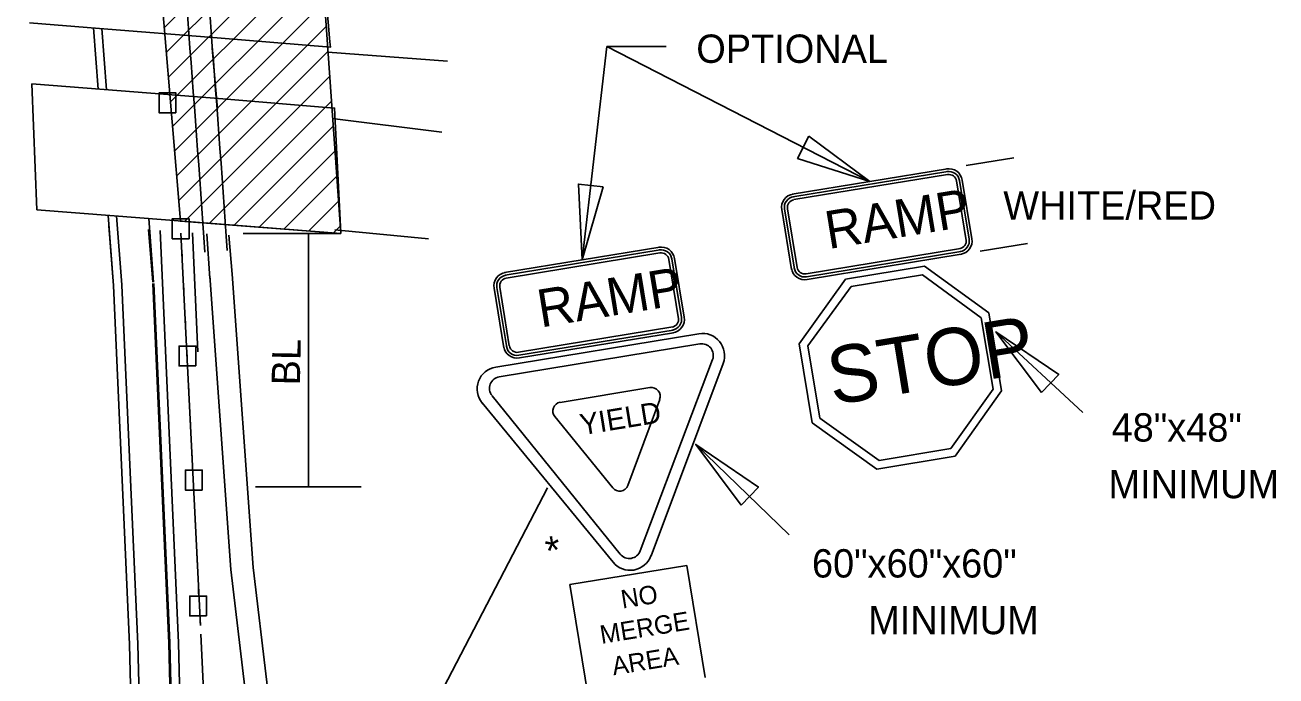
# Model space of a CAD drawing. Extents: x 612.5 to 619.9, y 600.8 to 610.9.
# Drawn here: x 615.494 to 618.141, y 606.093 to 607.471 of the extents above; entities that cross this region are included whole.
import ezdxf

# ---------------------------------------------------------------- set-up
doc = ezdxf.new("R2010")
doc.units = 0
for name, color, linetype in [('DETL-DIMS', 7, 'Continuous'), ('DETL-LINE', 7, 'Continuous'), ('DETL-NOTE', 7, 'Continuous')]:
    doc.layers.add(name, color=color, linetype=linetype)

msp = doc.modelspace()

# ---------------------------------------------------------------- linework, layer by layer
at = {"layer": 'DETL-DIMS'}
for p, q in [((616.6728, 606.9737), (616.7251, 607.4256)), ((616.7251, 607.4256), (617.2816, 607.1398)), ((616.8503, 607.4256), (616.7251, 607.4256)), ((617.4856, 607.1732), (617.5862, 607.1897)), ((616.162, 607.0297), (615.9552, 607.0297)), ((616.0936, 606.4929), (616.0936, 607.0279)), ((617.5152, 606.9922), (617.6154, 607.0086)), ((617.5486, 606.8214), (617.7323, 606.6507)), ((616.9133, 606.5829), (617.1111, 606.3914)), ((615.9818, 606.4929), (616.2054, 606.4929)), ((616.1815, 605.6878), (616.5998, 606.491))]:
    msp.add_line(p, q, dxfattribs=at)
for points in [[(617.1528, 607.2356), (617.1286, 607.1886), (617.2816, 607.1398)], [(616.7172, 607.128), (616.6648, 607.134), (616.6728, 606.9737)], [(617.6449, 606.693), (617.6813, 606.7311), (617.5486, 606.8214)], [(617.0096, 606.4546), (617.046, 606.4927), (616.9133, 606.5829)]]:
    msp.add_lwpolyline(points, close=True, dxfattribs=at)
at = {"layer": 'DETL-LINE'}
for p, q in [((615.7884, 607.4647), (616.1088, 607.7851)), ((615.7928, 607.4125), (616.1125, 607.7322)), ((615.7972, 607.3603), (616.1162, 607.6794)), ((615.8015, 607.3081), (616.12, 607.6265)), ((615.8059, 607.2559), (616.1237, 607.5737)), ((615.8103, 607.2037), (616.1274, 607.5208)), ((615.6384, 607.4649), (615.6486, 607.3353)), ((615.6563, 607.4634), (615.6665, 607.3339)), ((615.8147, 607.1515), (616.1311, 607.468)), ((615.819, 607.0993), (616.1348, 607.4151)), ((615.8896, 607.4221), (615.9011, 607.2929)), ((615.8896, 607.4221), (615.9011, 607.2929)), ((615.8896, 607.4221), (615.9011, 607.2929)), ((615.8317, 607.0554), (616.1386, 607.3623)), ((615.8841, 607.0513), (616.1423, 607.3094)), ((615.9366, 607.0472), (616.146, 607.2566)), ((615.9891, 607.0431), (616.1497, 607.2037)), ((617.4458, 607.1667), (617.1173, 607.1128)), ((616.0416, 607.039), (616.1534, 607.1509)), ((617.1185, 607.1071), (617.4467, 607.161)), ((617.1211, 607.1012), (617.446, 607.1546)), ((617.465, 607.1408), (617.4856, 607.0149)), ((617.4651, 607.1406), (617.465, 607.1408)), ((617.4716, 607.1418), (617.492, 607.0175)), ((617.4977, 607.0185), (617.4774, 607.1428)), ((616.0941, 607.035), (616.1571, 607.098)), ((615.6695, 607.068), (615.6812, 606.9196)), ((615.6875, 607.0666), (615.6988, 606.921)), ((615.7555, 607.0613), (615.766, 606.9262)), ((617.0954, 607.0801), (617.1162, 606.9533)), ((617.1219, 606.9545), (617.1012, 607.0811)), ((617.1276, 606.9578), (617.1072, 607.082)), ((615.6712, 607.0457), (615.6812, 606.9196)), ((615.6712, 607.0457), (615.6812, 606.9196)), ((615.6712, 607.0457), (615.6812, 606.9196)), ((615.7552, 607.0381), (615.764, 606.9262)), ((616.1466, 607.0309), (616.1609, 607.0452)), ((616.3477, 607.018), (616.1494, 607.0374)), ((615.8648, 606.1999), (615.8238, 607.0299)), ((615.8482, 607.0308), (615.8594, 606.779)), ((615.8851, 606.9346), (615.8786, 607.0285)), ((615.9248, 607.0259), (615.932, 606.9434)), ((615.9248, 607.0259), (615.932, 606.9434)), ((615.9248, 607.0259), (615.932, 606.9434)), ((615.9248, 607.0259), (615.932, 606.9434)), ((616.837, 607.0006), (616.5085, 606.9467)), ((616.5097, 606.941), (616.8378, 606.9948)), ((616.5123, 606.9352), (616.8372, 606.9885)), ((617.4737, 606.998), (617.1468, 606.9444)), ((617.4741, 606.9914), (617.1479, 606.9379)), ((617.1488, 606.9321), (617.4751, 606.9856)), ((616.8561, 606.9747), (616.8768, 606.8487)), ((616.8563, 606.9745), (616.8561, 606.9747)), ((616.8627, 606.9758), (616.8832, 606.8516)), ((616.889, 606.8525), (616.8686, 606.9768)), ((617.2305, 606.9332), (617.3974, 606.9606)), ((617.2305, 606.9332), (617.3974, 606.9606)), ((617.3974, 606.9606), (617.5334, 606.8615)), ((617.3974, 606.9606), (617.5334, 606.8615)), ((617.2305, 606.9332), (617.1321, 606.7962)), ((617.1321, 606.7962), (617.2305, 606.9332)), ((617.242, 606.917), (617.3928, 606.9417)), ((617.3928, 606.9417), (617.5175, 606.8512)), ((616.4866, 606.914), (616.5074, 606.7872)), ((616.5131, 606.7884), (616.4923, 606.915)), ((616.5187, 606.7918), (616.4984, 606.916)), ((617.242, 606.917), (617.1505, 606.7915)), ((617.5175, 606.8512), (617.5424, 606.6998)), ((617.5605, 606.6962), (617.5334, 606.8615)), ((617.5334, 606.8615), (617.5605, 606.6962)), ((616.8649, 606.8319), (616.538, 606.7783)), ((616.8652, 606.8252), (616.5391, 606.7718)), ((616.4898, 606.7469), (616.9196, 606.8174)), ((616.4974, 606.7262), (616.9216, 606.7958)), ((616.54, 606.766), (616.8663, 606.8195)), ((617.1596, 606.6288), (617.1321, 606.7962)), ((617.1596, 606.6288), (617.1321, 606.7962)), ((617.1505, 606.7915), (617.1756, 606.6385)), ((616.9488, 606.7626), (616.7957, 606.3574)), ((616.8186, 606.347), (616.9714, 606.7546)), ((616.8164, 606.7033), (616.6262, 606.6721)), ((616.8164, 606.7033), (616.8164, 606.7033)), ((617.5424, 606.6998), (617.4531, 606.5742)), ((617.5605, 606.6962), (617.4623, 606.5582)), ((617.5605, 606.6962), (617.4623, 606.5582)), ((616.7382, 606.3336), (616.4612, 606.6707)), ((616.7532, 606.3507), (616.4822, 606.6862)), ((616.7694, 606.4961), (616.8369, 606.6784)), ((616.6148, 606.6419), (616.7375, 606.4908)), ((617.3012, 606.5493), (617.1756, 606.6385)), ((617.2965, 606.5309), (617.1596, 606.6288)), ((617.2965, 606.5309), (617.1596, 606.6288)), ((617.4623, 606.5582), (617.2965, 606.5309)), ((617.4623, 606.5582), (617.2965, 606.5309)), ((617.3012, 606.5493), (617.4531, 606.5742)), ((616.6468, 606.2864), (616.8941, 606.327)), ((616.8941, 606.327), (616.933, 606.0896)), ((616.6468, 606.2864), (616.6857, 606.049)), ((615.8748, 605.9976), (615.8657, 606.181))]:
    msp.add_line(p, q, dxfattribs=at)
for points in [[(616.162, 607.0297), (615.8227, 607.0555), (615.664, 608.9494), (616.0287, 608.9238)], [(615.813, 607.2851), (615.7775, 607.2851), (615.7775, 607.3273), (615.813, 607.3273)], [(615.8408, 607.0184), (615.8053, 607.0184), (615.8053, 607.0606), (615.8408, 607.0606)], [(615.8554, 606.7491), (615.8199, 606.7491), (615.8199, 606.7913), (615.8554, 606.7913)], [(615.8687, 606.4864), (615.8332, 606.4864), (615.8332, 606.5286), (615.8687, 606.5286)], [(615.878, 606.2198), (615.8425, 606.2198), (615.8425, 606.262), (615.878, 606.262)]]:
    msp.add_lwpolyline(points, close=True, dxfattribs=at)
for points in [[(615.5034, 607.4759), (615.6514, 607.4639), (615.9007, 607.4435), (616.14, 607.424), (616.139, 607.4356), (616.1204, 607.6527), (616.1179, 607.6811), (615.878, 607.6997), (615.6314, 607.7187), (615.4938, 607.7293)], [(616.1346, 607.4137), (616.3877, 607.3943)], [(615.5084, 607.3467), (615.5185, 607.0799)], [(615.5185, 607.0799), (615.6825, 607.0671), (615.9359, 607.0472), (616.162, 607.0297), (616.1606, 607.0588), (616.149, 607.2952), (615.9122, 607.3143), (615.6615, 607.3343), (615.5084, 607.3467)], [(616.144, 607.2731), (616.3762, 607.2439)], [(615.743, 602.4107), (615.7794, 602.9085), (615.8185, 603.7952), (615.8337, 604.693), (615.8344, 605.528), (615.8187, 606.1632), (615.7799, 607.0362)], [(615.8261, 606.9821), (615.8257, 606.9908)], [(615.8266, 606.9731), (615.8261, 606.9821)], [(615.8847, 606.94), (615.9293, 606.3182), (615.9874, 605.8308), (616.0364, 605.4649), (616.065, 605.3359)], [(615.932, 606.9434), (615.9765, 606.3227), (616.0345, 605.8368), (616.0832, 605.4732), (616.1113, 605.3462)], [(615.932, 606.9434), (615.9765, 606.3227), (616.0345, 605.8368), (616.0832, 605.4732), (616.1113, 605.3462)], [(615.932, 606.9434), (615.9765, 606.3227), (616.0345, 605.8368), (616.0832, 605.4732), (616.1113, 605.3462)], [(615.932, 606.9434), (615.9765, 606.3227), (616.0345, 605.8368), (616.0832, 605.4732), (616.1113, 605.3462)], [(615.6811, 606.9197), (615.715, 606.1596), (615.7306, 605.5268), (615.7303, 605.1667)], [(615.6989, 606.9205), (615.7327, 606.1602), (615.7484, 605.5269), (615.7481, 605.1667)], [(615.7641, 606.9234), (615.798, 606.1625), (615.8137, 605.5277), (615.813, 604.6932), (615.7977, 603.7958), (615.7587, 602.9098), (615.7222, 602.4111)], [(615.7662, 606.9235), (615.8, 606.1626), (615.8157, 605.5277), (615.8154, 605.1666)], [(615.8296, 606.9109), (615.8293, 606.9198)], [(615.83, 606.902), (615.8296, 606.9109)], [(615.8332, 606.8398), (615.8328, 606.8488)], [(615.8336, 606.831), (615.8332, 606.8398)], [(615.8367, 606.7688), (615.8362, 606.7776)], [(615.8371, 606.7598), (615.8367, 606.7688)], [(615.8402, 606.6976), (615.8398, 606.7065)], [(615.8407, 606.6886), (615.8402, 606.6976)], [(615.8438, 606.6264), (615.8433, 606.6353)], [(615.8441, 606.6176), (615.8438, 606.6264)], [(615.8473, 606.5554), (615.8467, 606.5643)], [(615.8477, 606.5464), (615.8473, 606.5554)], [(615.8508, 606.4842), (615.8503, 606.4932)], [(615.8512, 606.4754), (615.8508, 606.4842)], [(615.8542, 606.4131), (615.8538, 606.4221)], [(615.8546, 606.4042), (615.8542, 606.4131)], [(615.8578, 606.342), (615.8573, 606.3508)], [(615.8582, 606.333), (615.8578, 606.342)], [(615.8612, 606.271), (615.8608, 606.2798)], [(615.8618, 606.262), (615.8612, 606.271)], [(615.8648, 606.1998), (615.8643, 606.2088)]]:
    msp.add_lwpolyline(points, dxfattribs=at)
for centre, radius, start, end in [((545.2135, 602.0274), 70.8825, 4.017322, 5.619484), ((545.2135, 602.0274), 70.8351, 4.017322, 5.619484), ((617.4487, 607.1379), 0.0289, 9.3163, 99.3163), ((617.4487, 607.1379), 0.0231, 9.3163, 99.3163), ((617.4487, 607.1379), 0.0166, 9.3163, 99.3163), ((617.1238, 607.0846), 0.0289, 99.3163, 189.3163), ((617.1238, 607.0846), 0.0231, 99.3163, 189.3163), ((617.1238, 607.0846), 0.0166, 99.3163, 189.3163), ((617.4691, 607.0139), 0.0166, 279.3163, 9.3163), ((617.4691, 607.0139), 0.0231, 279.3163, 9.3163), ((617.4691, 607.0139), 0.0289, 279.3163, 9.3163), ((616.8399, 606.9719), 0.0289, 9.3163, 99.3163), ((616.8399, 606.9719), 0.0231, 9.3163, 99.3163), ((616.8399, 606.9719), 0.0166, 9.3163, 99.3163), ((617.1442, 606.9606), 0.0289, 189.3163, 279.3163), ((617.1442, 606.9606), 0.0231, 189.3163, 279.3163), ((617.1442, 606.9606), 0.0166, 189.3163, 279.3163), ((616.515, 606.9186), 0.0289, 99.3163, 189.3163), ((616.515, 606.9186), 0.0231, 99.3163, 189.3163), ((616.515, 606.9186), 0.0166, 99.3163, 189.3163), ((616.8603, 606.8478), 0.0166, 279.3163, 9.3163), ((616.8603, 606.8478), 0.0231, 279.3163, 9.3163), ((616.8603, 606.8478), 0.0289, 279.3163, 9.3163), ((616.9273, 606.7711), 0.047, 339.4465, 99.3163), ((616.9257, 606.7715), 0.0247, 339.2893, 99.3163), ((616.5354, 606.7945), 0.0289, 189.3163, 279.3163), ((616.5354, 606.7945), 0.0231, 189.3163, 279.3163), ((616.5354, 606.7945), 0.0166, 189.3163, 279.3163), ((616.4975, 606.7005), 0.047, 99.3163, 219.4144), ((616.5014, 606.7018), 0.0247, 99.3163, 218.9277), ((616.8194, 606.6849), 0.0186, 339.7014, 99.3163), ((616.6293, 606.6538), 0.0186, 99.3163, 219.0611), ((616.752, 606.5026), 0.0186, 219.0611, 339.7014), ((616.7745, 606.3635), 0.047, 219.4144, 339.4465), ((616.7725, 606.3662), 0.0247, 218.9277, 339.2893)]:
    msp.add_arc(centre, radius, start, end, dxfattribs=at)

# ---------------------------------------------------------------- texts
for s, height, p in [('RAMP', 0.07987, (617.1941, 606.9964)), ('RAMP', 0.07987, (616.5852, 606.8304)), ('STOP', 0.12086, (617.2028, 606.666)), ('YIELD', 0.04472, (616.672, 606.6022)), ('NO', 0.03894, (616.7582, 606.2354)), ('MERGE', 0.03894, (616.7138, 606.1605)), ('AREA', 0.03894, (616.7392, 606.0941))]:
    msp.add_text(s, height=height, rotation=9.3163, dxfattribs=at).set_placement(p)
at = {"layer": 'DETL-NOTE'}
for s, p in [('OPTIONAL', (616.9144, 607.3908)), ('WHITE/RED', (617.5641, 607.059)), ('48"x48"', (617.7934, 606.589)), ('MINIMUM', (617.7868, 606.469)), ('60"x60"x60"', (617.1592, 606.3012)), ('MINIMUM', (617.2782, 606.1812))]:
    msp.add_text(s, height=0.06, dxfattribs=at).set_placement(p)
for s, rotation, p in [('BL', 88.9309, (616.0756, 606.7076)), ('*', 9.3163, (616.6009, 606.3267))]:
    msp.add_text(s, height=0.06, rotation=rotation, dxfattribs=at).set_placement(p)

doc.saveas('drawing.dxf')
